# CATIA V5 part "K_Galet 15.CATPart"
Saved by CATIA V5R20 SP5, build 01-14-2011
Part number: Galet 15
Bounding box of the stored display mesh (mm): x -69.996 to 69.996, y -15 to 15, z -69.998 to 69.998
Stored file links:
  G:\Khaled_CFAO_2011\SIL\SIL_GR1\gperrin\Khaled\CAD_CATIA\Khaled\K_Galet 15.CATPart
  G:\cfao\Projet\Product1 sans squelette.CATProduct
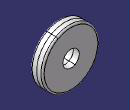
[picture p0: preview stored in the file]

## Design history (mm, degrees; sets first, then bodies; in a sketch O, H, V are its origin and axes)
External parameters (linked from other documents)
  `External.Raton 15 2` = 20 mm
Body1 (main body)
  Sketch1 on yz-plane, origin (0, 0, 0), H (0, 1, 0), V (0, 0, 1)
    point P1 (0, 70)
    line L1 (0, 70) -> (10.9813, 70)
    line L2 (15, 65.9813) -> (15, 20)
    point P2 (15, 70)
    point P3 (15, 20)
    arc A1 centre (10.9813, 65.9813) radius 4.0187 from (10.9813, 70) to (15, 65.9813) cw
    point P4 (10.9813, 70)
    point P5 (15, 65.9813)
    axis line L3 (0, 76) -> (0, -48)
    point P7 (0, 76)
    line L4 (15, 20) -> (0, 20)
    point P9 (0, 20)
    point P10 (0, 70)
    point P11 (-15, 70)
    point P12 (-15, 20)
    point P13 (-10.9813, 70)
    point P14 (-15, 65.9813)
    point P16 (0, 20)
    line L5 (0, 70) -> (-10.9813, 70)
    line L6 (-15, 65.9813) -> (-15, 20)
    arc A2 centre (-10.9813, 65.9813) radius 4.0187 from (-10.9813, 70) to (-15, 65.9813) ccw
    line L7 (-15, 20) -> (0, 20)
    distance L1 H = 70
    distance P1 P2 = 15
    radius A1 = 4.0187
    distance H L4 = 20 {= `External.Raton 15 2`}
    coincidence: P1 V, L1 P2, L2 P2, P7 V, P9 L3, P1 P10, P9 P16
    horizontal: L1 H, L4 H
    vertical: L2 V, L3 V
    tangency: A1 L1, A1 L2
    symmetry: P1 P10 L3, P2 P11 L3, P3 P12 L3, P4 P13 L3, P5 P14 L3, P9 P16 L3, L1 L5 L3, L2 L6 L3, A1 A2 L3, L4 L7 L3
  Shaft1: profile Sketch1, axis Sketch1.H, angle 360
